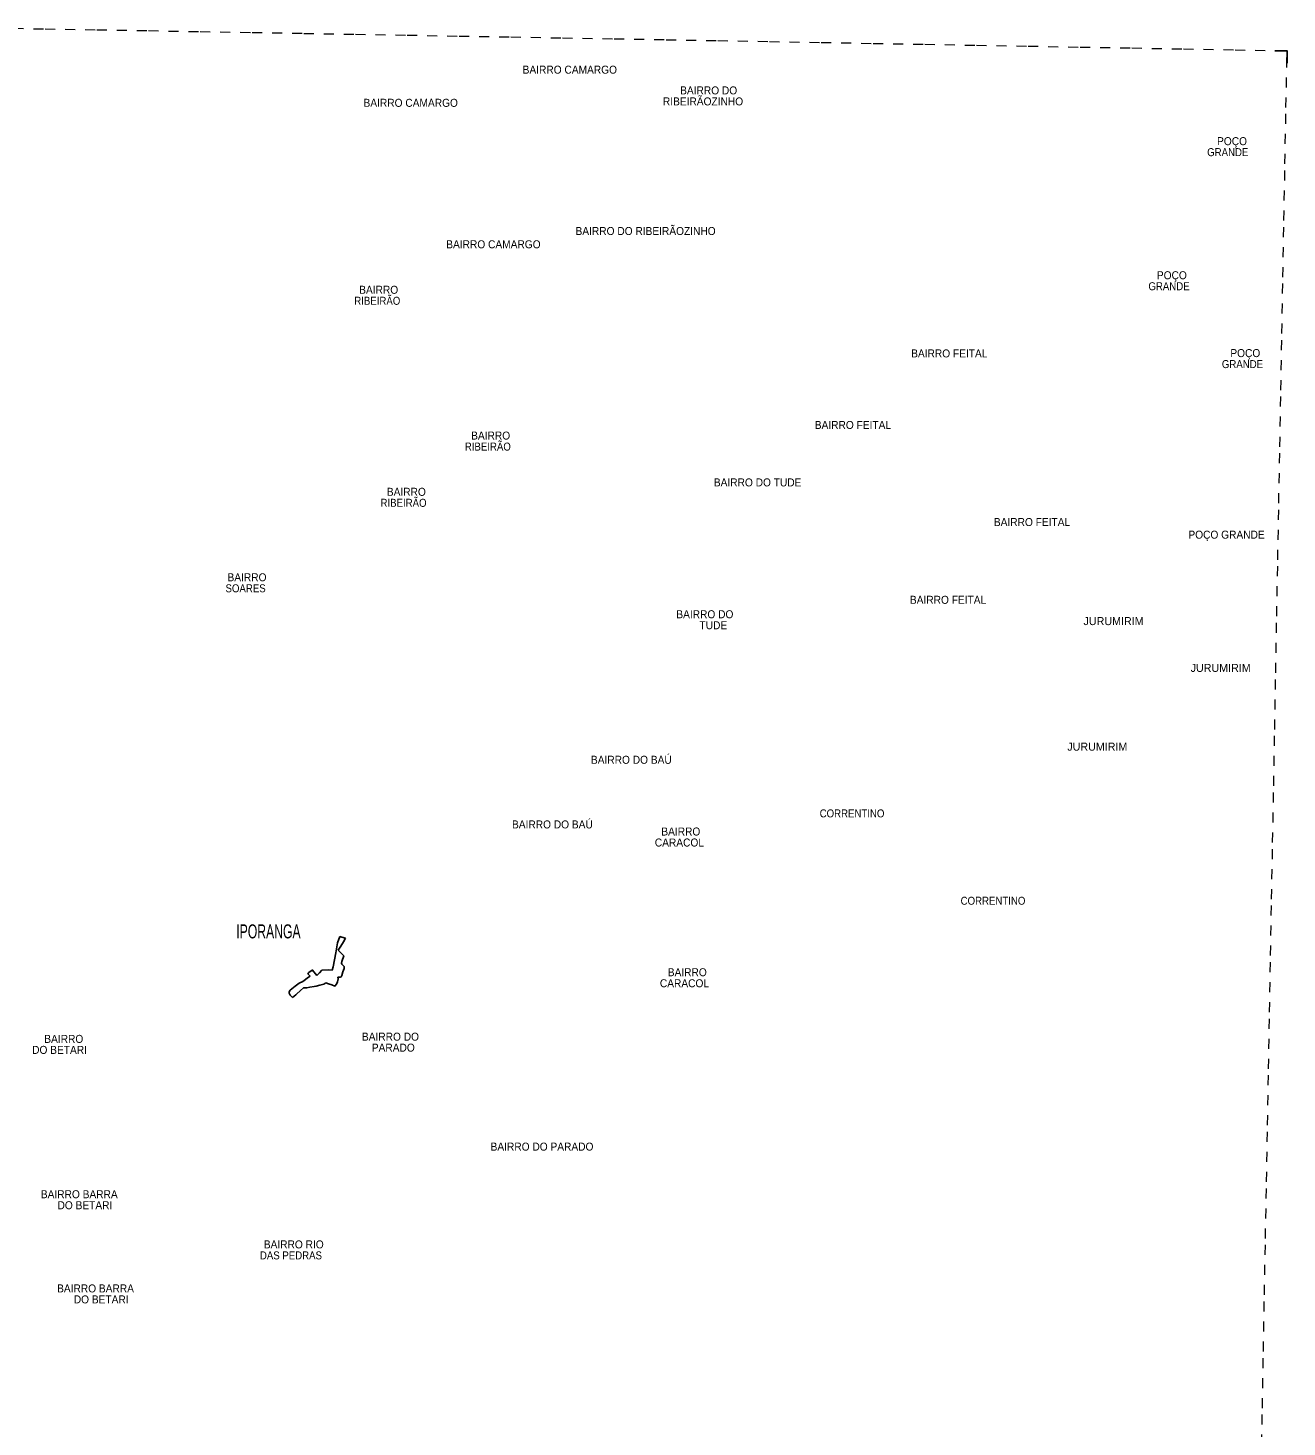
# Model space of a CAD drawing. Extents: x 727.5 to 753.3, y 7260.4 to 7288.5.
# Drawn here: x 740.76 to 753.34, y 7274.36 to 7288.34 of the extents above; entities that cross this region are included whole.
import ezdxf
from ezdxf.enums import TextEntityAlignment as Align

# ---------------------------------------------------------------- set-up
doc = ezdxf.new("R2010")
doc.units = 0
doc.header["$LTSCALE"] = 0.032
doc.linetypes.add('SHORT_DASHED', pattern=[2.7, 1.5, -1.2])
for name, color, linetype, lineweight in [('41', 7, 'Continuous', 25), ('46', 7, 'SHORT_DASHED', 13), ('63', 7, 'Continuous', 25)]:
    doc.layers.add(name, color=color, linetype=linetype, lineweight=lineweight)
doc.layers.add('61', color=7, linetype='Continuous')

msp = doc.modelspace()

# ---------------------------------------------------------------- linework, layer by layer
at = {"layer": '41'}
for points in [[(743.8718, 7279.2594), (743.8506, 7279.1963), (743.8308, 7279.0973), (743.8066, 7278.9564), (743.7956, 7278.9234), (743.756, 7278.9278), (743.6934, 7278.9241)], [(743.8569, 7279.1244), (743.8813, 7279.1624), (743.9103, 7279.2058), (743.9284, 7279.2419)], [(743.9284, 7279.2419), (743.8913, 7279.2519), (743.8718, 7279.2594)], [(743.8534, 7278.8527), (743.8754, 7278.8536), (743.8855, 7278.8573), (743.891, 7278.8683), (743.9029, 7278.9059), (743.9157, 7278.9398), (743.9166, 7278.9526), (743.9157, 7278.9591), (743.9075, 7278.9673), (743.891, 7278.9829), (743.8891, 7278.993), (743.891, 7279.0095), (743.9111, 7279.0663), (743.8569, 7279.1244)], [(743.5769, 7278.8618), (743.5497, 7278.8455), (743.5307, 7278.8283), (743.5017, 7278.8111), (743.4646, 7278.793), (743.4266, 7278.764), (743.3913, 7278.7368)], [(743.644, 7278.8704), (743.5997, 7278.9234), (743.5953, 7278.9212), (743.5623, 7278.8992), (743.5533, 7278.8853), (743.5769, 7278.8618)], [(743.6934, 7278.9241), (743.6689, 7278.8953), (743.644, 7278.8704)], [(743.7317, 7278.7966), (743.7597, 7278.7857), (743.7932, 7278.7758), (743.8231, 7278.7631), (743.838, 7278.7836), (743.8488, 7278.8071), (743.8542, 7278.8351), (743.8534, 7278.8527)], [(743.3913, 7278.7368), (743.3768, 7278.7224), (743.366, 7278.7052), (743.3651, 7278.6916), (743.3759, 7278.6726), (743.3994, 7278.6499)], [(743.3994, 7278.6499), (743.4311, 7278.6753), (743.4402, 7278.6825), (743.4791, 7278.7187), (743.5082, 7278.746)], [(743.5082, 7278.746), (743.5427, 7278.7464), (743.5739, 7278.7525), (743.6174, 7278.7605), (743.6343, 7278.7645)], [(743.6343, 7278.7645), (743.672, 7278.7733), (743.7112, 7278.7844), (743.7317, 7278.7966)]]:
    msp.add_lwpolyline(points, dxfattribs=at)
at = {"layer": '46'}
for points in [[(740.4091, 7288.3404), (740.9263, 7288.3315), (741.4435, 7288.3226), (741.9607, 7288.3137), (742.4779, 7288.3047), (742.9951, 7288.2957), (743.5123, 7288.2868), (744.0295, 7288.2777), (744.5467, 7288.2687), (745.064, 7288.2597), (745.5812, 7288.2506), (746.0984, 7288.2415), (746.6156, 7288.2324), (747.1328, 7288.2233), (747.6501, 7288.2141), (748.1673, 7288.205), (748.6845, 7288.1958), (749.2017, 7288.1866), (749.719, 7288.1774), (750.2362, 7288.1681), (750.7534, 7288.1589), (751.2706, 7288.1496), (751.7879, 7288.1403), (752.3051, 7288.131), (752.8223, 7288.1216), (753.3396, 7288.1123)], [(753.0831, 7273.9806), (753.0934, 7274.5459), (753.1037, 7275.1112), (753.1139, 7275.6765), (753.1242, 7276.2417), (753.1345, 7276.807), (753.1448, 7277.3723), (753.155, 7277.9375), (753.1653, 7278.5028), (753.1756, 7279.0681), (753.1858, 7279.6333), (753.1961, 7280.1986), (753.2064, 7280.7639), (753.2166, 7281.3291), (753.2269, 7281.8944), (753.2371, 7282.4596), (753.2474, 7283.0249), (753.2576, 7283.5902), (753.2679, 7284.1554), (753.2781, 7284.7207), (753.2884, 7285.286), (753.2986, 7285.8512), (753.3089, 7286.4165), (753.3191, 7286.9818), (753.3293, 7287.547), (753.3396, 7288.1123)]]:
    msp.add_lwpolyline(points, dxfattribs=at)
at = {"layer": '63'}
msp.add_lwpolyline([(753.3395, 7287.9891), (753.3395, 7288.1123), (753.2181, 7288.1123)], dxfattribs=at)

# ---------------------------------------------------------------- texts
at = {"layer": '61'}
for s, width, p in [('BAIRRO CAMARGO', 0.95, (746.17125, 7287.8836)), ('    BAIRRO DO', 0.95, (747.5024, 7287.6766)), ('BAIRRO CAMARGO', 0.95, (744.58095, 7287.5524)), ('RIBEIRÃOZINHO', 0.95, (747.5024, 7287.5666)), ('   POÇO', 0.95, (752.74755, 7287.1692)), ('GRANDE', 0.9, (752.7475, 7287.0592)), ('BAIRRO DO RIBEIRÃOZINHO', 0.95, (746.9284, 7286.2711)), ('BAIRRO CAMARGO', 0.95, (745.40765, 7286.1383)), ('GRANDE', 0.9, (752.1603, 7285.7189)), ('   POÇO ', 0.95, (752.16035, 7285.8289)), ('RIBEIRÃO', 0.9, (744.24675, 7285.5737)), ('  BAIRRO ', 0.95, (744.24675, 7285.6837)), ('BAIRRO FEITAL', 0.95, (749.9641, 7285.0475)), ('   POÇO ', 0.95, (752.89445, 7285.0508)), ('GRANDE', 0.9, (752.8944, 7284.9408)), ('BAIRRO FEITAL', 0.95, (749.0007, 7284.3323)), ('  BAIRRO', 0.95, (745.35165, 7284.2262)), ('RIBEIRÃO', 0.9, (745.35165, 7284.1162)), ('BAIRRO DO TUDE', 0.95, (748.04845, 7283.7582)), ('  BAIRRO', 0.95, (744.50915, 7283.6642)), ('RIBEIRÃO', 0.9, (744.50915, 7283.5542)), ('BAIRRO FEITAL', 0.95, (750.7908, 7283.3621)), ('POÇO GRANDE', 0.95, (752.73515, 7283.2358)), (' BAIRRO', 0.95, (742.93055, 7282.8099)), ('SOARES', 0.9, (742.9305, 7282.6999)), ('BAIRRO FEITAL', 0.95, (749.9517, 7282.5847)), ('BAIRRO DO ', 0.95, (747.535, 7282.4404)), ('     TUDE', 0.95, (747.535, 7282.3304)), ('BAIRRO DO BAÚ', 0.95, (746.786, 7280.9858)), ('CORRENTINO', 0.9, (748.992, 7280.4499)), ('BAIRRO DO BAÚ', 0.95, (745.997, 7280.3397)), ('  BAIRRO ', 0.95, (747.26645, 7280.2688)), ('CARACOL', 0.95, (747.2665, 7280.1588)), ('CORRENTINO', 0.9, (750.4009, 7279.5768)), ('  BAIRRO', 0.95, (747.31695, 7278.862)), ('CARACOL', 0.95, (747.317, 7278.752)), ('   BAIRRO', 0.95, (741.07095, 7278.1961)), ('BAIRRO DO', 0.95, (744.3785, 7278.2183)), ('DO BETARI', 0.95, (741.0709, 7278.0861)), ('  PARADO', 0.95, (744.37845, 7278.1083)), ('BAIRRO DO PARADO', 0.95, (745.89325, 7277.1191)), ('BAIRRO BARRA', 0.95, (741.26815, 7276.6432)), ('    DO BETARI', 0.95, (741.2682, 7276.5332)), ('  BAIRRO RIO', 0.95, (743.38365, 7276.1419)), ('DAS PEDRAS', 0.9, (743.38365, 7276.0319)), ('BAIRRO BARRA', 0.95, (741.43055, 7275.7019)), ('    DO BETARI', 0.95, (741.4306, 7275.5919))]:
    msp.add_text(s, height=0.08, dxfattribs=dict(at, width=width)).set_placement(p, align=Align.CENTER)
for p in [(751.606, 7282.372), (752.6765, 7281.9041), (751.4435, 7281.1169)]:
    msp.add_text('JURUMIRIM', height=0.08, dxfattribs=at).set_placement(p, align=Align.CENTER)
at = {"layer": '61', "width": 0.65}
msp.add_text('IPORANGA', height=0.14, dxfattribs=at).set_placement((743.48, 7279.2407), align=Align.RIGHT)

doc.saveas('drawing.dxf')
